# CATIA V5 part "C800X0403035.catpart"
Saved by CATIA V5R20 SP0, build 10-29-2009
Part number: C800X0403035
Source: Unknown
Property "A": "40"
Property "ARTICLENO": "C800X0403035"
Property "B": "18"
Property "BOMINFO": "C800X0403035"
Property "C": "70"
Property "CA": "C800X0403035"
Property "D1": "58"
Property "DES": "ROTATING EYEBOLT WITH RING Ton 4,0 M30x35"
Property "E": "68"
Property "H": "153"
Property "L": "35"
Property "LINA": "C800X0403035"
Property "NB": "C800X0403035"
Property "NBSYN": "$CODE."
Property "NN": "C800X"
Property "NT": "Rotating eyebolt with ring"
Property "SIZE": "M30"
Property "SUPPLIER": "CF"
Property "SW": "48"
Property "WEIGHT": "1630"
Property "WLL": "4.00"
Bounding box of the stored display mesh (mm): x -38 to 38, y -35 to 171, z -29 to 29
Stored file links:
  C:\Users\Utente\Desktop\3D files 800X\C800X0403035.catpart
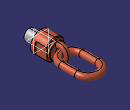
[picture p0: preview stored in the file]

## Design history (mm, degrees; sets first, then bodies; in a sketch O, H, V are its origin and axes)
Body1 "Geometry.1" (main body)
  Solid1 "C800X0403035.catpart": solid without history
